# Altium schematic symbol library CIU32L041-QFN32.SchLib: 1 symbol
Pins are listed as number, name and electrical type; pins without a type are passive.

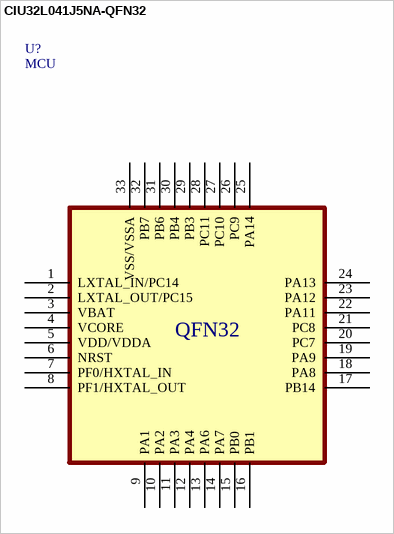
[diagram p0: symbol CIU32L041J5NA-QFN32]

## CIU32L041J5NA-QFN32
designator U?, comment MCU
footprint CIU32L041-QFN-32N (QFN, 32-Leads, Body 4.1x4.1mm (max), Pitch 0.40mm, IPC Medium Density)
pins: 1 LXTAL_IN/PC14, 2 LXTAL_OUT/PC15, 3 VBAT, 4 VCORE, 5 VDD/VDDA, 6 NRST, 7 PF0/HXTAL_IN, 8 PF1/HXTAL_OUT, 9 PA1, 10 PA2, 11 PA3, 12 PA4, 13 PA6, 14 PA7, 15 PB0, 16 PB1, 17 PB14, 18 PA8, 19 PA9, 20 PC7, 21 PC8, 22 PA11, 23 PA12, 24 PA13, 25 PA14, 26 PC9, 27 PC10, 28 PC11, 29 PB3, 30 PB4, 31 PB6, 32 PB7, 33 VSS/VSSA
